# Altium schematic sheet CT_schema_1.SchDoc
size 474 x 258 mm
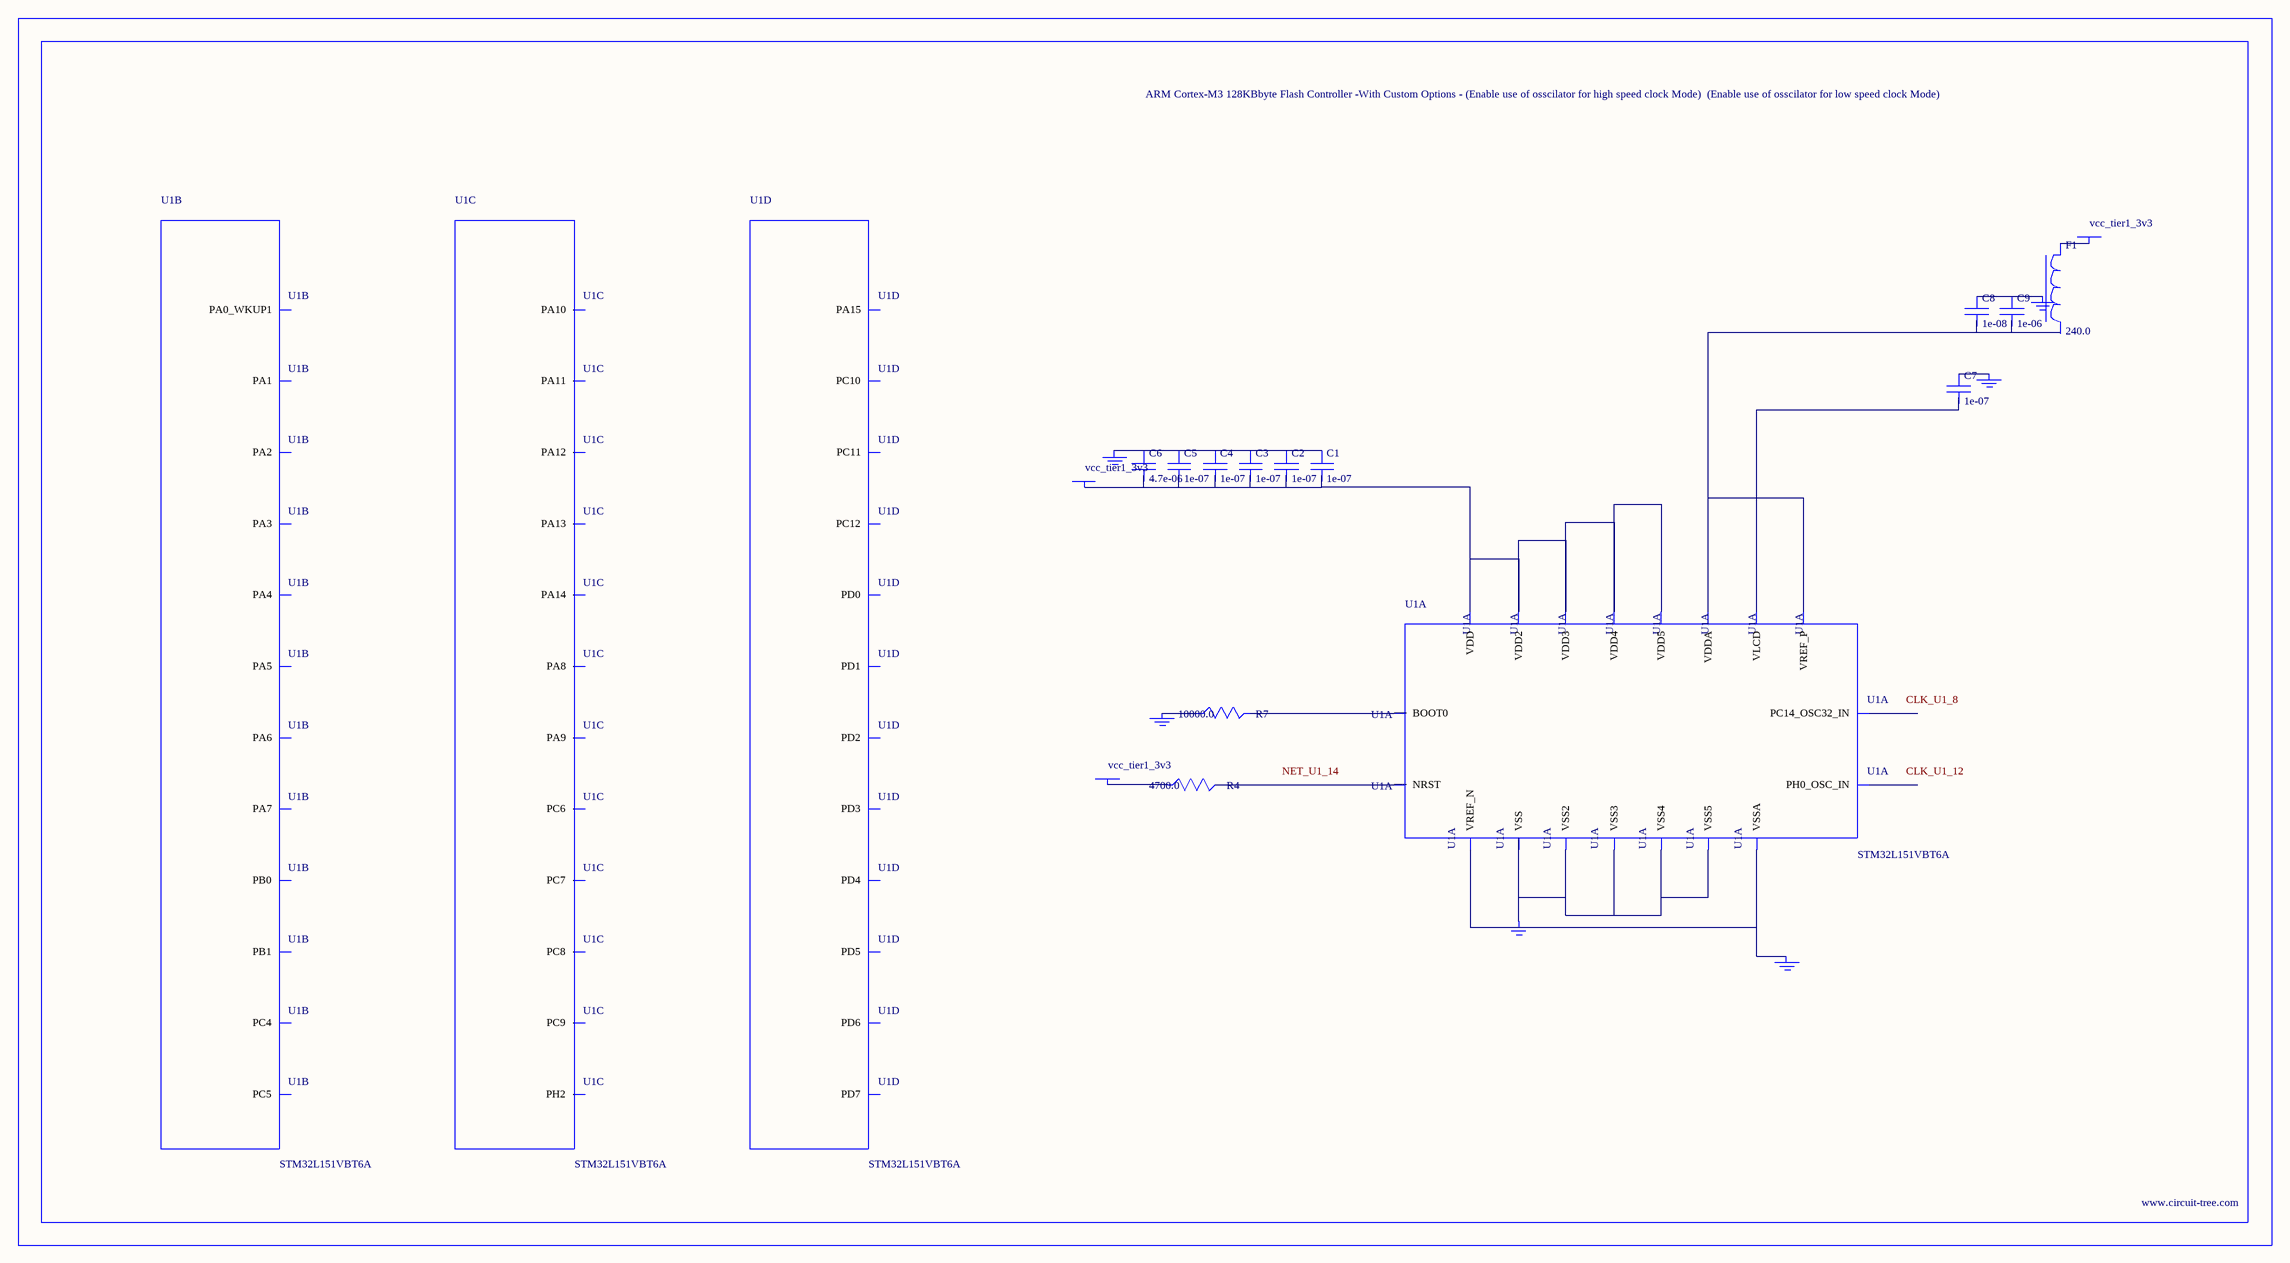
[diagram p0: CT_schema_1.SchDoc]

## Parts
BORDER0  (no value)
C1  1e-07  [C0603]
C2  1e-07  [C0603]
C3  1e-07  [C0603]
C4  1e-07  [C0603]
C5  1e-07  [C0603]
C6  4.7e-06  [C0603]
C7  1e-07  [C0603]
C8  1e-08  [C0603]
C9  1e-06  [C0603]
F1  240.0  [L0603]
GND_INSTANCE_0_0  (no value)
GND_INSTANCE_0_1  (no value)
GND_INSTANCE_0_2  (no value)
GND_INSTANCE_0_3  (no value)
GND_INSTANCE_0_4  (no value)
GND_INSTANCE_0_5  (no value)
POWER_INSTANCE_0_0  vcc_tier1_3v3
POWER_INSTANCE_0_1  vcc_tier1_3v3
POWER_INSTANCE_0_2  vcc_tier1_3v3
R4  4700.0  [R0603]
R7  10000.0  [R0603]
U1  STM32L151VBT6A  [LQFP100]  (parts A,B,C,D of 8)

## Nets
NetC1_1: C1.1 C2.1 C3.1 C4.1 C5.1 C6.1 GND_INSTANCE_0_1.0(GND)
NetC1_2: C1.2 C2.2 C3.2 C4.2 C5.2 C6.2 POWER_INSTANCE_0_0.0(PWR) U1.11(VDD) U1.28(VDD2) U1.50(VDD3) U1.75(VDD4) U1.100(VDD5)
NetC7_1: C7.1 GND_INSTANCE_0_0.0(GND)
NetC7_2: C7.2 U1.6(VLCD)
NetC8_1: C8.1 C9.1 GND_INSTANCE_0_3.0(GND)
NetC8_2: C8.2 C9.2 U1.21(VREF_P) U1.22(VDDA)
NetF1_1: F1.1 POWER_INSTANCE_0_1.0(PWR)
NetGND_INSTANCE_0_2_0: GND_INSTANCE_0_2.0(GND) U1.19(VSSA) U1.20(VREF_N)
NetGND_INSTANCE_0_4_0: GND_INSTANCE_0_4.0(GND) R7.1
NetGND_INSTANCE_0_5_0: GND_INSTANCE_0_5.0(GND) U1.10(VSS) U1.27(VSS2) U1.49(VSS3) U1.74(VSS4) U1.99(VSS5)
NetPOWER_INSTANCE_0_2_0: POWER_INSTANCE_0_2.0(PWR) R4.1
NetR4_2: R4.2 U1.14(NRST)
NetR7_2: R7.2 U1.94(BOOT0)

Not connected (* = marked no-connect by the designer): F1 2; U1 8(PC14_OSC32_IN) 12(PH0_OSC_IN) 23(PA0_WKUP1) 24(PA1) 25(PA2) 26(PA3) 29(PA4) 30(PA5) 31(PA6) 32(PA7) 33(PC4) 34(PC5) 35(PB0) 36(PB1) 63(PC6) 64(PC7) 65(PC8) 66(PC9) 67(PA8) 68(PA9) 69(PA10) 70(PA11) 71(PA12) 72(PA13) 73(PH2) 76(PA14) 77(PA15) 78(PC10) 79(PC11) 80(PC12) 81(PD0) 82(PD1) 83(PD2) 84(PD3) 85(PD4) 86(PD5) 87(PD6) 88(PD7)

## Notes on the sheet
- Labels drawn without touching a wire or pin: CLK_U1_8, CLK_U1_12, NET_U1_14

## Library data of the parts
BORDER0 = BORDER_PAGE0
C1-C5 C7 = 06035C104K4Z2A
C6 = GRM188R6YA475KE15D
C8 = 06035C103K4Z2A
C9 = C0603C105K3RACTU
F1 = Z0603C241ASMST
GND_INSTANCE_0_0-GND_INSTANCE_0_5 = GND
POWER_INSTANCE_0_0-POWER_INSTANCE_0_2 = PWR
R4 = RC0603JR-074K7L
R7 = RC0603JR-0710KL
